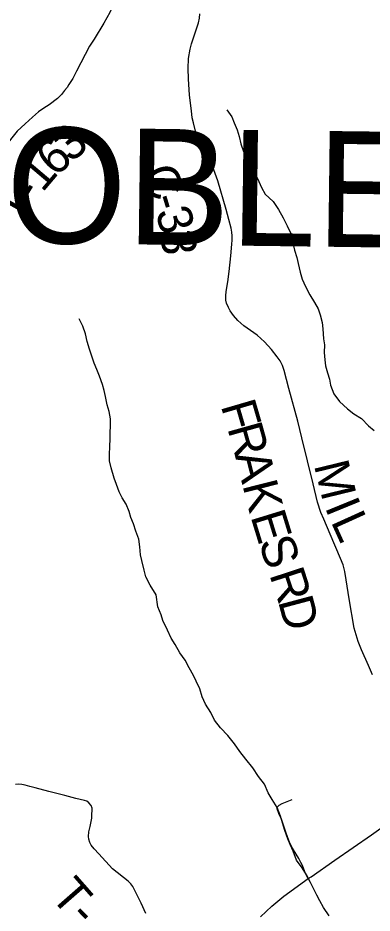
# Model space of a CAD drawing. Extents: x 0 to 191, y 0 to 55.
# Drawn here: x 145.722 to 146.011, y 24.084 to 24.816 of the extents above; entities that cross this region are included whole.
import ezdxf

# ---------------------------------------------------------------- set-up
doc = ezdxf.new("R2010")
doc.units = 0
for name, color, linetype in [('GM_X_County_Road', 7, 'Continuous'), ('GM_X_County_Road_Text', 7, 'Continuous'), ('GM_X_County_Text', 7, 'Continuous'), ('GM_X_Minor_River', 7, 'Continuous'), ('GM_X_State_Route', 7, 'Continuous'), ('GM_X_Township_Road', 7, 'Continuous'), ('GM_X_Township_Road_Text', 7, 'Continuous')]:
    doc.layers.add(name, color=color, linetype=linetype)

msp = doc.modelspace()

# ---------------------------------------------------------------- linework, layer by layer
at = {"layer": 'GM_X_County_Road'}
msp.add_lwpolyline([(146.01164, 24.27914), (146.00837, 24.28652), (146.0027, 24.29952), (145.99997, 24.30637), (145.99671, 24.31729), (145.9927, 24.34131), (145.99024, 24.35671), (145.98895, 24.36367), (145.98756, 24.36896), (145.98564, 24.37405), (145.97713, 24.39411), (145.97178, 24.40646), (145.96948, 24.41192), (145.96665, 24.42032), (145.96306, 24.43514), (145.95397, 24.47301), (145.95065, 24.48644), (145.94332, 24.51335), (145.93952, 24.52806), (145.93819, 24.53202), (145.93615, 24.53577), (145.93385, 24.53908), (145.92904, 24.54518), (145.92347, 24.55133), (145.91754, 24.55674), (145.90662, 24.56444), (145.9017, 24.56883), (145.89801, 24.573), (145.89539, 24.57669), (145.89389, 24.57942), (145.89229, 24.58295), (145.8917, 24.58557), (145.8917, 24.58916), (145.89213, 24.59263), (145.89336, 24.6005), (145.89459, 24.609), (145.89592, 24.62174), (145.89673, 24.63126), (145.89699, 24.63468), (145.89694, 24.63816), (145.89678, 24.64126), (145.89619, 24.64442), (145.89437, 24.65153), (145.89213, 24.65977), (145.88538, 24.68299), (145.88201, 24.69208), (145.87934, 24.69845), (145.87356, 24.71027), (145.86704, 24.72375), (145.86538, 24.73049), (145.86441, 24.73461), (145.86366, 24.7405), (145.86206, 24.75323), (145.86136, 24.76644), (145.86094, 24.775), (145.86131, 24.78324), (145.86265, 24.79084), (145.86366, 24.79517), (145.865, 24.79929), (145.86853, 24.80914), (145.8695, 24.81235), (145.87035, 24.81614), (145.87062, 24.81978)], dxfattribs=at)
at = {"layer": 'GM_X_Minor_River'}
for points in [[(145.89264, 24.74107), (145.89663, 24.73539), (145.89854, 24.73065), (145.90102, 24.72477), (145.90274, 24.71926), (145.90409, 24.71338), (145.90638, 24.70712), (145.91019, 24.7003), (145.91382, 24.69328), (145.91668, 24.68721), (145.91877, 24.68247), (145.92106, 24.67754), (145.92392, 24.67223), (145.93058, 24.66617), (145.93477, 24.65954), (145.93877, 24.6529), (145.94201, 24.64627), (145.94506, 24.64001), (145.94641, 24.63355), (145.94794, 24.62634), (145.94986, 24.62027), (145.95101, 24.61552), (145.95254, 24.6085), (145.95427, 24.60281), (145.95694, 24.59674), (145.96037, 24.58991), (145.96437, 24.58365), (145.96723, 24.57834), (145.96895, 24.57341), (145.97067, 24.56715), (145.97107, 24.56202), (145.97166, 24.55385), (145.97243, 24.54891), (145.97226, 24.54264), (145.97265, 24.53657), (145.97323, 24.53182), (145.97496, 24.52612), (145.97649, 24.52081), (145.97745, 24.51587), (145.98012, 24.50885), (145.98469, 24.5026), (145.99135, 24.49654), (145.99648, 24.49257), (146.00276, 24.4886), (146.00827, 24.48273), (146.01303, 24.47875)], [(145.83502, 24.3445), (145.82999, 24.35245), (145.82654, 24.35907), (145.82519, 24.36457), (145.82306, 24.37253), (145.82208, 24.37727), (145.82148, 24.38372), (145.82068, 24.38998), (145.81837, 24.39661), (145.81626, 24.40249), (145.81433, 24.4076), (145.81279, 24.41272), (145.81048, 24.41859), (145.80704, 24.42369), (145.80455, 24.4288), (145.80243, 24.43468), (145.80051, 24.43998), (145.79819, 24.44832), (145.79683, 24.45401), (145.7968, 24.45913), (145.79714, 24.46578), (145.79729, 24.47204), (145.79727, 24.47679), (145.79761, 24.48286), (145.79758, 24.48856), (145.7966, 24.49444), (145.79486, 24.49993), (145.7935, 24.50657), (145.79233, 24.51169), (145.79117, 24.51642), (145.78847, 24.52343), (145.78636, 24.52874), (145.78425, 24.53385), (145.78251, 24.53896), (145.78039, 24.5454), (145.77866, 24.55166), (145.77729, 24.55791), (145.77498, 24.56435), (145.77192, 24.57022)], [(145.97631, 24.08178), (145.97155, 24.0886), (145.9685, 24.0941), (145.96621, 24.09884), (145.96374, 24.10358), (145.96107, 24.10927), (145.95764, 24.11553), (145.95421, 24.12121), (145.94945, 24.12746), (145.94677, 24.13467), (145.94429, 24.14017), (145.94238, 24.14492), (145.94009, 24.15156), (145.93817, 24.15782), (145.93645, 24.16332), (145.93378, 24.17053), (145.92978, 24.17698), (145.92654, 24.18248), (145.92348, 24.1895), (145.91853, 24.19594), (145.91377, 24.20295), (145.90806, 24.21015), (145.9033, 24.21622), (145.89892, 24.22266), (145.8934, 24.22929), (145.8875, 24.23573), (145.88255, 24.2418), (145.8795, 24.24825), (145.87531, 24.25507), (145.87245, 24.26095), (145.87053, 24.2676), (145.86748, 24.27385), (145.86538, 24.2786), (145.86176, 24.28467), (145.85852, 24.29092), (145.85433, 24.29699), (145.85033, 24.30382), (145.84728, 24.30894), (145.84422, 24.31558), (145.84041, 24.32335), (145.83907, 24.3281), (145.83639, 24.33455), (145.83502, 24.3445)]]:
    msp.add_lwpolyline(points, dxfattribs=at)
at = {"layer": 'GM_X_State_Route'}
msp.add_lwpolyline([(145.92006, 24.08107), (145.9294, 24.08982), (145.93912, 24.09789), (145.95923, 24.11228), (145.96155, 24.11389), (145.98099, 24.1275), (146.01082, 24.14813), (146.02697, 24.15949)], dxfattribs=at)
at = {"layer": 'GM_X_Township_Road'}
for points in [[(145.80195, 24.83186), (145.79714, 24.82085), (145.79212, 24.81202), (145.78411, 24.79904), (145.78051, 24.79321), (145.76982, 24.77281), (145.76671, 24.76681), (145.7636, 24.76191), (145.76208, 24.75945), (145.76011, 24.757), (145.75744, 24.75384), (145.75417, 24.75045), (145.74757, 24.74533), (145.74305, 24.74255), (145.73868, 24.73966), (145.73393, 24.73524), (145.72783, 24.72973), (145.72145, 24.72379), (145.71698, 24.71817), (145.71022, 24.70917), (145.70624, 24.70394), (145.69942, 24.69581), (145.69517, 24.69111)], [(145.82655, 24.0838), (145.82261, 24.09233), (145.81968, 24.0981), (145.81588, 24.1058), (145.81417, 24.10807), (145.81207, 24.11035), (145.79916, 24.12032), (145.78814, 24.13253), (145.78425, 24.1366), (145.78189, 24.13957), (145.78062, 24.14189), (145.77987, 24.14451), (145.77952, 24.14683), (145.77983, 24.15064), (145.78088, 24.15484), (145.78224, 24.16188), (145.78237, 24.16494), (145.78254, 24.16792), (145.7825, 24.17002), (145.78175, 24.1722), (145.78, 24.17443), (145.7783, 24.17557), (145.77646, 24.17614), (145.76929, 24.17776), (145.76019, 24.18025), (145.74711, 24.18353), (145.73595, 24.18655), (145.73167, 24.18764), (145.72782, 24.18887), (145.72502, 24.18939), (145.72266, 24.18957), (145.71999, 24.18939)], [(145.95923, 24.11228), (145.95792, 24.1144), (145.95639, 24.11797), (145.95537, 24.12084), (145.95445, 24.12293), (145.95321, 24.12561), (145.95158, 24.12884), (145.94927, 24.13241), (145.94623, 24.13718), (145.9442, 24.1414), (145.94121, 24.14962), (145.93721, 24.16107), (145.93518, 24.16557), (145.93382, 24.16932), (145.93388, 24.17065), (145.93536, 24.17228), (145.93773, 24.17366), (145.94047, 24.17489), (145.94595, 24.17696)]]:
    msp.add_lwpolyline(points, dxfattribs=at)

# ---------------------------------------------------------------- texts
at = {"layer": 'GM_X_County_Road_Text'}
for s, rotation, p in [('C', 291.34772, (145.82243, 24.69004)), ('-', 286.8772, (145.83073, 24.66887)), ('3', 286.14198, (145.83409, 24.65779)), ('3', 273.98959, (145.83868, 24.64255)), ('F', 286.29784, (145.88753, 24.4993)), ('R', 285.68164, (145.89289, 24.48098)), ('A', 284.18733, (145.89915, 24.4587)), ('M', 283.7139, (145.96369, 24.45074)), ('K', 284.19189, (145.90528, 24.43446)), ('I', 292.2838, (145.97241, 24.41645)), ('E', 287.09541, (145.91183, 24.40871)), ('L', 294.41296, (145.97729, 24.40461)), ('S', 288.45647, (145.9183, 24.3877)), ('R', 288.17947, (145.92716, 24.36121)), ('D', 284.98962, (145.93432, 24.33944))]:
    msp.add_text(s, height=0.02841, rotation=rotation, dxfattribs=at).set_placement(p)
at = {"layer": 'GM_X_County_Text'}
msp.add_text('NOBLE COUNTY', height=0.094697, rotation=359.28458, dxfattribs=at).set_placement((145.62033, 24.63362))
at = {"layer": 'GM_X_Township_Road_Text'}
for s, rotation, p in [('3', 41.6828, (145.76546, 24.6973)), ('6', 42.10286, (145.75252, 24.6856)), ('1', 49.78197, (145.74192, 24.67296)), ('T', 60.56076, (145.72621, 24.64565)), ('-', 58.64666, (145.73652, 24.66394)), ('T', 311.24277, (145.74767, 24.09758)), ('-', 313.98422, (145.76268, 24.08051))]:
    msp.add_text(s, height=0.02841, rotation=rotation, dxfattribs=at).set_placement(p)

doc.saveas('drawing.dxf')
